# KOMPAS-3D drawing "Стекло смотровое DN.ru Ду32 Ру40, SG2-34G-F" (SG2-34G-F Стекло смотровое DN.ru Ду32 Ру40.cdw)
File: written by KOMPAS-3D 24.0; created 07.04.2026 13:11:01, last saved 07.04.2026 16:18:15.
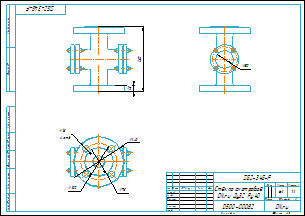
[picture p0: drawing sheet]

Document properties: Автор: Main; Форматы листов документа: A3; Полное имя файла: SG2-34G-F Стекло смотровое DN.ru Ду32 Ру40.m3d; Масса: 6.2; Наименование: Стекло смотровое DN.ru Ду32 Ру40; Количество листов документа: 1; Примечание: D500-00082

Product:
- Body: Тело 1  | qty 1
    Масса: 6.03947
- Part/product: Стекло смотровое DN.ru Ду32 Ру40  | designation SG2-34G-F
    Масса: 6.2
    Раздел спецификации: Прочие изделия
    Примечание: D500-00082

Views: Вид 1, Снизу, Проекционный вид 2
Referenced files in D:\DN.ru Аутсерс\Стекло смотровое DN.ru\Стекло смотровое DN.ru SG2-34G-F тип В ГОСТ 21836-2021 Ду100 Ру16, углеродистая сталь, фланцевое\: SG2-34G-F тип В Стекло смотровое DN.ru Ду100 Ру16.m3d, SG2-34G-F тип ВСтекло смотровое DN.ru Ду100 Ру16.cdw
Referenced files in D:\DN.ru Аутсерс\Стекло смотровое DN.ru\SG2-34G-F Стекло смотровое DN.ru Ду32 Ру40\: SG2-34G-F Стекло смотровое DN.ru Ду32 Ру40.m3d
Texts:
  SG2-34G-F
  Стекло смотровое
  DN.ru Ду32 Ру40
  Стекло смотровое DN.ru Ду32 Ру40
  SG2-34G-F Стекло смотровое DN.ru Ду32 Ру40
Dimensions and other numbers on the sheet: 0; 3; 2; 4; 180; 18; 4 отв.; 100; 78; 140; 1:2; 1; 6,2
